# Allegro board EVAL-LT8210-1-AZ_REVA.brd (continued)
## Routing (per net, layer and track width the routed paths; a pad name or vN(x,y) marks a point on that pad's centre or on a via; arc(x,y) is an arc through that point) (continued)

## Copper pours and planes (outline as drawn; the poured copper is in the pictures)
GND_POWER on TOP: 66.04,222.88 176.35,222.88 176.35,149.35 138.23,149.35 137.97,149.61 137.97,164.59 137.59,164.97 103.48,164.97 102.03,163.52 102.03,149.02 59.39,149.02 59.39,162.81 32.51,162.81 32.51,218.19 54.86,218.19 55.17,218.49 55.17,220.85 66.04,220.85 ; 1 cut-out
GND_POWER on TOP: 190.2,160.45 190.2,156.79 195.63,156.79 195.63,160.45
GND_POWER on TOP: 66.04,133.1 176.35,133.1 176.35,62.23 138.18,62.23 137.92,62.48 137.92,77.34 137.41,77.85 103.48,77.85 102.03,76.4 102.03,61.72 59.39,61.72 59.39,75.56 32.51,75.56 32.51,128.4 54.86,128.4 55.17,128.7 55.17,131.19 66.04,131.19
GND_POWER on TOP: 66.04,312.67 176.35,312.67 176.35,239.4 138.21,239.4 137.96,239.65 137.96,254.5 137.58,254.88 103.48,254.88 101.98,253.38 101.98,239.45 60.01,239.45 60.01,252.73 32.51,252.73 32.51,307.97 54.86,307.97 55.17,308.28 55.17,310.77 66.04,310.77
GND_POWER on TOP: 12.06,160.45 12.06,156.79 17.5,156.79 17.5,160.45
GND_POWER on TOP: 66.32,45.85 176.35,45.85 176.35,2.54 32.51,2.54 32.51,41.15 54.86,41.15 55.17,41.45 55.17,43.57 66.32,43.57
GND_POWER on TOP: 32.65,356.62 32.65,342.54 59.87,342.54 59.87,328.6 101.98,328.6 101.98,343.19 103.48,344.69 137.58,344.69 137.96,344.31 137.96,329.18 138.21,328.93 176.35,328.93 176.35,356.62
GND_POWER on TOP, L5_VCC: 6.98,174.5 22.23,174.5
GND_POWER on TOP, L5_VCC: 185.29,196.72 200.53,196.72
GND_POWER on TOP, L5_VCC: 6.98,197.36 22.23,197.36
GND_POWER on TOP, L5_VCC: 185.29,173.86 200.53,173.86
GND_POWER on BOTTOM: 32.51,356.62 203.2,356.62 203.2,2.54 32.51,2.54 32.51,162.8 2.54,162.8 2.54,209.03 31.6,209.03 32.51,209.94
GND_POWER on L2_GND, L3_SIG, L4_GND, L5_VCC: 2.54,356.62 203.2,356.62 203.2,2.54 2.54,2.54
VDD on TOP: 51.86,22.99 51.86,21.86 51.55,21.86 51.41,21.72 51.41,20.45 50.62,20.45 50.62,22.22 46.76,22.22 46.69,22.3 46.69,22.91 46.76,22.99
VDD on TOP: 50.8,30.48 50.8,30.1 53.09,30.1 53.09,30.61 52.2,31.5 51.82,31.5
VIN on TOP: 72.39,171.96 72.39,167.89 73.28,167.01 92.58,167.01 94.61,169.04 94.61,173.36 93.09,173.36 93.09,170.43 91.06,168.4 75.56,168.4 74.29,169.67 74.29,171.96
VIN on TOP: 76.58,91.57 75.95,92.2 25.4,92.2 24,90.8 24,89.53 25.53,88.01 76.45,88.01 76.58,88.14
VIN on TOP: 32.02,356.62 32.02,2.54 2.67,2.54 2.67,356.62
VIN on TOP: 67.83,178.05 30.99,178.05 30.99,173.36 65.28,173.36 67.94,170.69 74.29,170.69 74.29,172.59 75.06,173.36 75.06,174.62 71.24,174.62
VIN on BOTTOM: 31.8,162.17 2.54,162.17 2.54,2.54 31.98,2.54 31.98,161.99
VIN on BOTTOM: 31.32,209.72 2.54,209.72 2.54,356.62 31.85,356.62 31.85,210.25
VIN on L2_GND, L3_SIG, L4_GND: 7.11,273.69 22.35,273.69
VIN on L2_GND, L3_SIG, L4_GND: 7.11,94.36 22.35,94.36
VIN on L5_VCC: 32.02,356.62 32.02,2.54 2.67,2.54 2.67,356.62
(no net) on TOP: 115.71,30.61 115.71,31.9 115.67,31.94 114.1,31.94 113.8,31.65 112.46,31.65 112.46,30.85 112.7,30.61
(no net) on TOP: 112.57,26.37 112.29,26.37 112.29,26.85 111.66,27.48 111.66,29.26 111.81,29.41 112.42,29.41 112.57,29.26
(no net) on L3_SIG: 91.95,63.37 94.74,60.58 94.74,40.87 106.38,29.24 111.79,29.24 111.94,29.39 112.32,29.39 112.5,29.21 112.5,28.14 105.97,28.14 93.73,40.39 93.73,60.07 91.31,62.48 69.71,62.48 69.58,62.6 69.58,63.75 69.71,63.88 70.87,63.88 70.99,63.75 70.99,63.5 71.12,63.37 82.7,63.37 82.7,63.75 82.83,63.88 83.57,63.88 83.69,63.75 83.69,63.5 83.82,63.37
EXTVCC_1 on TOP (solid shape): 115.71,31.9 115.71,30.61 112.7,30.61 112.46,30.85 112.46,31.65 113.8,31.65 114.1,31.94 115.67,31.94
EXTVCC_2 on TOP: 115.71,117.86 115.71,119.15 115.67,119.19 114.1,119.19 113.8,118.9 112.46,118.9 112.46,118.1 112.7,117.86
EXTVCC_3 on TOP: 115.71,207.64 115.71,208.94 115.67,208.98 114.1,208.98 113.8,208.69 112.46,208.69 112.46,207.89 112.7,207.64
EXTVCC_4 on TOP: 115.71,297.43 115.71,298.73 115.67,298.77 114.1,298.77 113.8,298.48 112.46,298.48 112.46,297.68 112.7,297.43
UNNAMED_2_ADLT82101_I27_SW1 on TOP: 95.78,73.23 95.78,62.57 95.99,62.37 101.68,62.37 102.02,62.71 102.02,73.2 101.82,73.41 95.96,73.41
UNNAMED_2_ADLT82101_I27_SW1 on TOP: 71.92,64.39 71.92,62.61 71.99,62.43 72.17,62.36 75.65,62.36 75.83,62.43 75.91,62.61 75.91,68.12 75.83,68.3 75.65,68.38 75.43,68.38 75.33,68.4 75.25,68.45 75.17,68.53 75.11,68.61 75.1,68.71 75.1,73.15 74.97,73.28 70.65,73.28 70.57,73.2 70.57,68.8 70.55,68.7 70.5,68.62 70.33,68.45 70.25,68.4 70.15,68.38 69.84,68.38 69.66,68.3 69.58,68.12 69.58,64.52 71.79,64.52
UNNAMED_2_ADLT82101_I27_SW1 on TOP: 88.91,62.65 88.84,62.47 88.66,62.4 85.12,62.4 84.94,62.47 84.86,62.65 84.86,66.04 84.73,66.17 82.7,66.17 82.7,68.12 82.78,68.3 82.96,68.38 83.16,68.38 83.25,68.4 83.34,68.45 83.47,68.58 83.52,68.66 83.54,68.76 83.54,73.15 83.67,73.28 87.99,73.28 88.01,73.25 88.01,68.79 88.03,68.69 88.09,68.61 88.23,68.46 88.31,68.41 88.41,68.39 88.66,68.39 88.84,68.32 88.91,68.14
UNNAMED_2_ADLT82101_I27_SW1 on BOTTOM: 69.82,73.41 69.57,73.15 69.57,62.73 70.07,62.23 76.43,62.23 76.56,62.36 76.56,63.88 76.68,64.01 84.81,64.01 84.94,63.88 84.94,62.36 85.19,62.1 89,62.1 89.26,62.36 89.26,63.88 89.38,64.01 95.58,64.01 95.58,62.36 101.35,62.36 101.35,73.41
UNNAMED_2_ADLT82101_I27_SW1 on L5_VCC: 69.82,73.41 69.57,73.15 69.57,62.36 101.35,62.36 101.35,73.41
UNNAMED_2_ADLT82101_I27_SW2 on TOP: 159.44,62.23 159.26,62.3 159.18,62.48 159.18,66.04 159.05,66.17 157.1,66.17 157.1,68.07 157.17,68.25 157.35,68.33 157.64,68.33 157.74,68.35 157.82,68.4 157.91,68.49 157.97,68.58 157.99,68.67 157.99,73.1 158.04,73.15 162.36,73.15 162.41,73.1 162.41,68.66 162.43,68.56 162.48,68.48 162.56,68.4 162.64,68.35 162.74,68.33 163.04,68.33 163.22,68.25 163.3,68.07 163.3,62.48 163.22,62.3 163.04,62.23
UNNAMED_2_ADLT82101_I27_SW2 on TOP: 122.94,77.22 122.68,76.96 122.68,46.74 122.94,46.48 137.05,46.48 137.3,46.74 137.3,76.96 137.05,77.22
UNNAMED_2_ADLT82101_I27_SW2 on TOP: 150.29,62.48 150.22,62.3 150.04,62.23 146.43,62.23 146.25,62.3 146.18,62.48 146.18,64.44 146.05,64.57 144.11,64.57 144.11,68.07 144.18,68.25 144.36,68.33 144.62,68.33 144.72,68.35 144.8,68.4 144.91,68.51 144.96,68.59 144.98,68.69 144.98,73.1 145.03,73.15 149.35,73.15 149.4,73.1 149.4,68.63 149.42,68.54 149.48,68.46 149.53,68.4 149.61,68.35 149.71,68.33 150.04,68.33 150.22,68.25 150.29,68.07
UNNAMED_2_ADLT82101_I27_SW2 on BOTTOM: 122.94,77.22 122.68,76.96 122.68,46.74 122.96,46.46 136.89,46.46 137.3,46.86 137.3,61.62 137.92,62.24 163,62.24 163.31,62.55 163.31,72.9 162.8,73.41 142.62,73.41 142.24,73.79 142.24,74.55 142.11,74.68 137.54,74.68 137.29,74.93 137.29,76.83 136.91,77.22
UNNAMED_2_ADLT82101_I27_SW2 on L5_VCC: 122.94,77.22 122.68,76.96 122.68,46.74 122.96,46.46 136.89,46.46 137.93,47.5 137.93,61.35 138.19,61.61 162.37,61.61 163.31,62.55 163.31,72.9 162.8,73.41 142.62,73.41 142.24,73.79 142.24,74.55 142.11,74.68 137.54,74.68 137.29,74.93 137.29,76.83 136.91,77.22
UNNAMED_2_ADLT82101_I27_TG1 on TOP (solid shape): 112.57,29.26 112.57,26.37 112.29,26.37 112.29,26.85 111.66,27.48 111.66,29.26 111.81,29.41 112.42,29.41
UNNAMED_2_ADLT82101_I27_TG1 on L3_SIG (solid shape): 70.99,63.75 70.99,63.5 71.12,63.37 82.7,63.37 82.7,63.75 82.83,63.88 83.57,63.88 83.69,63.75 83.69,63.5 83.82,63.37 91.95,63.37 94.74,60.58 94.74,40.87 106.38,29.24 111.79,29.24 111.94,29.39 112.32,29.39 112.5,29.21 112.5,28.14 105.97,28.14 93.73,40.39 93.73,60.07 91.31,62.48 69.71,62.48 69.58,62.6 69.58,63.75 69.71,63.88 70.87,63.88
UNNAMED_2_ADLT82101_I27_TG2 on L3_SIG: 141.66,63.8 157.75,63.8 157.75,62.41 141.78,62.41 127.63,48.26 127.63,30.28 121.77,24.41 118.85,24.41 118.77,24.49 118.77,25.76 118.87,25.86 121.28,25.86 126.62,31.19 126.62,48.77
UNNAMED_2_ADLT82101_I27_VIN on TOP: 111.33,23.88 111.33,23.57 109.85,23.57 109.47,23.19 107.75,23.19 107.54,22.99 105,22.99 105,26.72 106.98,26.72 109.83,23.88
UNNAMED_2_CAP_I39_N1 on TOP: 28.04,47.18 28.04,44.15 32,44.15 32,47.05 31.88,47.18
UNNAMED_2_CAP_I39_N1 on TOP: 30.09,59.57 30.09,58.35 30.21,58.22 31.86,58.22 31.99,58.35 31.99,59.57 31.88,59.68 30.2,59.68
UNNAMED_2_CAP_I39_N1 on L3_SIG: 30.23,59.82 30.23,45.85 30.48,45.59 31.75,45.59 32,45.85 32,59.82 31.88,59.94 30.35,59.94
UNNAMED_2_CAP_I149_N2 on TOP: 176.35,61.59 176.34,57.91 173.99,57.91 173.99,56.13 176.28,56.13 176.35,46.48 138.16,46.48 137.93,46.71 137.93,61.34 138.19,61.59
UNNAMED_2_CAP_I149_N2 on BOTTOM: 138.19,61.61 137.93,61.35 137.93,46.71 138.19,46.46 175.94,46.46 176.35,46.86 176.35,61.29 176.03,61.61
UNNAMED_2_CAP_I149_N2 on L5_VCC: 138.19,61.61 137.93,61.35 137.93,46.71 138.19,46.46 175.04,46.46 176.39,47.8 176.39,61.21 176,61.61
UNNAMED_2_CAPP_I42_N1 on TOP: 32.77,75.06 59.37,75.06 59.37,61.72 96.32,61.72 96.32,59.42 106.17,59.42 106.17,46.61 106.04,46.48 61.34,46.48 61.34,53.98 59.39,53.98 59.39,46.48 55.12,46.48 54.58,45.95 54.58,42.19 54.18,41.78 32.89,41.78 32.64,42.04 32.64,74.93
UNNAMED_2_CAPP_I42_N1 on BOTTOM: 32.88,75.06 59.39,75.06 59.39,61.72 96.33,61.72 96.33,59.31 106.17,59.31 106.17,46.61 106.04,46.48 55.12,46.48 54.58,45.95 54.58,42.19 54.18,41.78 33.01,41.78 32.63,42.16 32.63,74.8
UNNAMED_2_CAPP_I42_N1 on L5_VCC: 32.88,75.06 59.39,75.06 59.39,61.72 96.33,61.72 96.33,59.31 106.17,59.31 106.17,46.61 106.04,46.48 61.34,46.48 61.34,53.34 59.39,53.34 59.39,46.48 55.12,46.48 54.58,45.95 54.58,42.19 54.18,41.78 33.01,41.78 32.63,42.16 32.63,74.8
UNNAMED_2_IND_I187_N1 on TOP: 121.79,77.22 103.68,77.22 102.65,76.19 102.65,62.71 103.01,62.36 107.76,62.36 108.25,61.86 108.25,59.93 107.75,59.42 106.81,59.42 106.81,46.48 121.67,46.48 121.92,46.74 121.92,77.09
UNNAMED_2_IND_I187_N1 on BOTTOM, L5_VCC: 121.79,77.22 103.68,77.22 103.38,76.91 103.38,62.81 103.63,62.56 106.81,62.56 106.81,46.48 121.92,46.48 121.92,77.09
UNNAMED_2_NCTESTPAD_I95_N1 on TOP: 69.83,75.44 71.07,75.44 71.18,75.33 71.18,73.94 71.16,73.91 69.84,73.91 69.7,74.06 69.7,75.31
UNNAMED_2_NCTESTPAD_I95_N1 on TOP: 82.84,75.42 84.09,75.42 84.2,75.31 84.2,73.94 84.17,73.91 82.86,73.91 82.73,74.04 82.73,75.31
UNNAMED_2_NCTESTPAD_I95_N1 on L3_SIG: 70.74,75.44 70.87,75.31 70.87,74.93 70.99,74.8 78.61,74.8 78.74,74.93 78.74,75.18 78.87,75.31 80.01,75.31 80.14,75.18 80.14,74.93 80.26,74.8 82.4,74.8 82.52,74.93 82.52,75.31 82.65,75.44 83.44,75.44 83.57,75.31 83.57,74.93 83.67,74.83 108.05,74.83 110.49,72.39 110.49,43.93 119.72,34.7 119.72,33.52 118.47,33.52 118.47,34.48 109.6,43.35 109.6,72.01 107.57,74.04 69.63,74.04 69.51,74.17 69.51,75.31 69.63,75.44
UNNAMED_2_NCTESTPAD_I107_N1 on TOP: 158.67,75.31 158.67,73.91 158.55,73.79 157.21,73.79 157.1,73.9 157.1,75.31 157.23,75.44 158.55,75.44
UNNAMED_2_NCTESTPAD_I107_N1 on TOP: 144.24,75.44 145.54,75.44 145.67,75.31 145.67,73.91 145.54,73.79 144.22,73.79 144.09,73.91 144.09,75.29
UNNAMED_2_NCTESTPAD_I107_N1 on L3_SIG: 143.18,75.23 157.75,75.23 157.75,73.86 143.33,73.86 121.51,52.04 121.51,33.52 120.24,33.52 120.24,52.3
UNNAMED_3_ADLT82101_I10_SW1 on TOP: 95.78,250.15 95.78,239.66 95.99,239.46 101.69,239.46 101.98,239.75 101.98,250.11 101.77,250.33 95.96,250.33
UNNAMED_3_ADLT82101_I10_SW1 on TOP: 71.87,241.33 71.87,239.5 71.89,239.47 75.65,239.47 75.83,239.55 75.91,239.73 75.91,245.16 75.83,245.34 75.65,245.41 75.4,245.41 75.31,245.43 75.22,245.49 75.07,245.65 75.01,245.73 74.99,245.82 74.99,250.05 74.71,250.33 70.7,250.33 70.57,250.2 70.57,245.84 70.55,245.74 70.5,245.66 70.28,245.44 70.2,245.38 70.1,245.36 69.82,245.36 69.64,245.29 69.57,245.11 69.57,241.55 71.64,241.55
UNNAMED_3_ADLT82101_I10_SW1 on TOP: 88.89,239.71 88.81,239.53 88.63,239.46 85.09,239.46 84.91,239.53 84.84,239.71 84.84,242.82 84.45,243.21 82.72,243.21 82.72,245.16 82.79,245.34 82.97,245.41 83.17,245.41 83.27,245.43 83.35,245.49 83.52,245.66 83.57,245.74 83.59,245.84 83.59,250.11 83.79,250.32 87.63,250.32 88.01,249.94 88.01,245.82 88.03,245.73 88.09,245.65 88.24,245.49 88.32,245.43 88.42,245.41 88.63,245.41 88.81,245.34 88.89,245.16
UNNAMED_3_ADLT82101_I10_SW1 on BOTTOM: 69.82,250.44 69.57,250.19 69.57,239.45 76.56,239.45 76.56,240.92 76.68,241.05 84.81,241.05 84.94,240.92 84.94,239.45 89.26,239.45 89.26,240.92 89.38,241.05 95.58,241.05 95.58,239.45 101.35,239.45 101.35,250.44
UNNAMED_3_ADLT82101_I10_SW1 on L5_VCC: 69.82,250.33 69.57,250.08 69.57,239.45 101.35,239.45 101.35,250.33
UNNAMED_3_ADLT82101_I10_SW2 on TOP: 150.29,239.65 150.22,239.47 150.04,239.4 146.43,239.4 146.25,239.47 146.18,239.65 146.18,241.49 146.05,241.62 144.11,241.62 144.11,245.11 144.18,245.29 144.36,245.36 144.64,245.36 144.73,245.38 144.82,245.44 144.91,245.53 144.96,245.61 144.98,245.71 144.98,250.16 149.15,250.16 149.4,249.91 149.4,245.7 149.42,245.6 149.48,245.52 149.56,245.44 149.64,245.38 149.74,245.36 150.04,245.36 150.22,245.29 150.29,245.11
UNNAMED_3_ADLT82101_I10_SW2 on TOP: 159.51,239.34 159.33,239.42 159.26,239.6 159.26,242.82 158.88,243.21 157.11,243.21 157.11,245.11 157.19,245.29 157.37,245.36 157.64,245.36 157.74,245.38 157.82,245.44 157.91,245.53 157.97,245.61 157.99,245.71 157.99,250.09 162.15,250.09 162.39,249.85 162.39,245.71 162.41,245.61 162.47,245.53 162.56,245.44 162.64,245.38 162.74,245.36 163.03,245.36 163.21,245.29 163.28,245.11 163.28,239.6 163.21,239.42 163.03,239.34
UNNAMED_3_ADLT82101_I10_SW2 on TOP: 122.94,254.25 122.68,254 122.68,223.77 122.94,223.52 136.79,223.52 137.17,223.9 137.17,253.87 136.79,254.25
UNNAMED_3_ADLT82101_I10_SW2 on BOTTOM: 122.94,254.25 122.68,254 122.68,223.77 122.96,223.49 136.75,223.49 137.16,223.9 137.16,238.72 137.78,239.34 162.99,239.34 163.3,239.65 163.3,249.94 162.79,250.44 142.62,250.44 142.24,250.82 142.24,251.59 142.11,251.71 137.41,251.71 137.16,251.97 137.16,253.87 136.78,254.25
UNNAMED_3_ADLT82101_I10_SW2 on L5_VCC: 122.94,254.25 122.68,254 122.68,223.77 122.96,223.49 136.75,223.49 137.16,223.9 137.16,238.24 137.64,238.72 163,238.72 163.31,239.03 163.31,249.94 162.8,250.44 142.62,250.44 142.24,250.82 142.24,251.59 142.11,251.71 137.41,251.71 137.16,251.97 137.16,253.87 136.78,254.25
UNNAMED_3_ADLT82101_I10_TG1 on TOP: 112.57,203.4 112.29,203.4 112.29,203.89 111.66,204.52 111.66,206.3 111.81,206.45 112.42,206.45 112.57,206.3
UNNAMED_3_ADLT82101_I10_TG1 on L3_SIG: 91.69,240.41 94.74,237.36 94.74,217.91 106.37,206.27 111.81,206.27 111.96,206.43 112.34,206.43 112.5,206.27 112.5,205.18 105.97,205.18 93.73,217.42 93.73,236.86 91.06,239.52 69.71,239.52 69.58,239.64 69.58,240.79 69.71,240.92 70.87,240.92 70.99,240.79 70.99,240.54 71.12,240.41 82.7,240.41 82.7,240.79 82.83,240.92 83.57,240.92 83.69,240.79 83.69,240.54 83.82,240.41
UNNAMED_3_ADLT82101_I10_TG2 on TOP: 120.45,202.63 120.37,202.81 120.19,202.89 119.24,202.89 119.09,202.82 119.02,202.67 119.02,201.64 119.09,201.51 119.23,201.46 120.19,201.46 120.37,201.54 120.45,201.72
UNNAMED_3_ADLT82101_I10_TG2 on L3_SIG: 141.4,240.84 157.91,240.84 157.91,239.4 141.48,239.4 127.63,225.55 127.63,207.31 121.77,201.45 119.13,201.45 118.97,201.6 118.97,202.79 119.13,202.95 121.39,202.95 126.62,208.18 126.62,226.06
UNNAMED_3_ADLT82101_I10_VIN on TOP: 111.33,200.91 111.33,200.61 109.85,200.61 109.47,200.23 107.75,200.23 107.54,200.02 105,200.02 105,203.76 106.98,203.76 109.83,200.91
UNNAMED_3_CAP_I22_N1 on TOP: 28.02,224.21 28.02,221.21 32,221.21 32,224.21
UNNAMED_3_CAP_I22_N1 on TOP: 30.1,236.61 30.1,235.39 30.23,235.27 31.88,235.27 32,235.39 32,236.61 31.89,236.73 30.21,236.73
UNNAMED_3_CAP_I22_N1 on L3_SIG: 30.23,236.85 30.23,222.88 30.48,222.63 31.75,222.63 32,222.88 32,236.85 31.88,236.98 30.35,236.98
UNNAMED_3_CAP_I128_N2 on TOP: 176.35,238.71 176.35,234.7 174.12,234.7 174.12,232.92 176.35,232.92 176.35,223.52 138.05,223.52 137.79,223.77 137.79,238.51 138,238.71
UNNAMED_3_CAP_I128_N2 on BOTTOM: 138.05,238.71 137.79,238.46 137.79,223.75 138.05,223.49 176.04,223.49 176.36,223.81 176.36,238.34 175.99,238.71
UNNAMED_3_CAP_I128_N2 on L5_VCC: 138.05,238.71 137.79,238.46 137.79,223.75 138.05,223.49 174.83,223.49 176.39,225.06 176.39,238.34 176.02,238.71
UNNAMED_3_CAPP_I25_N1 on TOP: 32.64,251.97 32.64,219.1 32.89,218.85 54.11,218.85 54.52,219.25 54.52,222.99 55.05,223.52 59.39,223.52 59.39,231.01 61.34,231.01 61.34,223.52 105.92,223.52 106.04,223.65 106.04,236.47 96.32,236.47 96.32,238.82 59.39,238.82 59.39,252.09 32.77,252.09
UNNAMED_3_CAPP_I25_N1 on BOTTOM: 32.77,252.09 59.39,252.09 59.39,238.76 96.32,238.76 96.32,236.47 106.04,236.47 106.04,223.65 105.92,223.52 55.12,223.52 54.58,222.99 54.58,219.1 54.18,218.69 32.89,218.69 32.51,219.07 32.51,251.84
UNNAMED_3_CAPP_I25_N1 on L5_VCC: 32.89,252.09 59.39,252.09 59.39,238.76 96.32,238.76 96.32,236.47 106.17,236.47 106.17,223.65 106.04,223.52 61.34,223.52 61.34,230.38 59.39,230.38 59.39,223.52 55.12,223.52 54.58,222.99 54.58,219.1 54.18,218.69 33.02,218.69 32.64,219.07 32.64,251.84
UNNAMED_3_IND_I87_N1 on TOP: 121.79,254.25 103.68,254.25 102.62,253.19 102.62,239.76 102.95,239.43 107.76,239.43 108.25,238.94 108.25,237.02 107.71,236.47 106.68,236.47 106.68,223.52 121.67,223.52 121.92,223.77 121.92,254.13
UNNAMED_3_IND_I87_N1 on BOTTOM, L5_VCC: 121.79,254.25 103.68,254.25 103.38,253.95 103.38,239.85 103.63,239.6 106.68,239.6 106.68,223.52 121.92,223.52 121.92,254.13
UNNAMED_3_NCTESTPAD_I76_N1 on TOP: 69.84,252.48 71.06,252.48 71.18,252.35 71.18,251.09 71.06,250.96 69.85,250.96 69.72,251.1 69.72,252.35
UNNAMED_3_NCTESTPAD_I76_N1 on TOP: 82.84,252.49 84.06,252.49 84.2,252.35 84.2,251.09 84.07,250.96 82.92,250.96 82.73,251.16 82.73,252.37
UNNAMED_3_NCTESTPAD_I76_N1 on L3_SIG: 70.74,252.48 70.87,252.35 70.87,251.97 70.99,251.84 78.61,251.84 78.74,251.97 78.74,252.22 78.87,252.35 80.01,252.35 80.14,252.22 80.14,251.97 80.26,251.84 82.4,251.84 82.52,251.97 82.52,252.35 82.65,252.48 83.44,252.48 83.57,252.35 83.57,251.97 83.67,251.87 108.05,251.87 110.49,249.43 110.49,220.97 119.72,211.73 119.72,210.55 118.47,210.55 118.47,211.52 109.6,220.38 109.6,249.05 107.57,251.08 69.63,251.08 69.51,251.21 69.51,252.35 69.63,252.48
UNNAMED_3_NCTESTPAD_I88_N1 on TOP: 158.67,252.4 158.67,251.08 158.53,250.93 157.24,250.93 157.11,251.07 157.11,252.38 157.25,252.53 158.55,252.53
UNNAMED_3_NCTESTPAD_I88_N1 on TOP: 145.67,252.22 145.67,250.97 145.56,250.86 144.4,250.86 144.27,250.99 144.27,252.21 144.37,252.31 145.58,252.31
UNNAMED_3_NCTESTPAD_I88_N1 on L3_SIG: 143.18,252.27 157.75,252.27 157.75,250.9 143.33,250.9 121.51,229.08 121.51,210.55 120.24,210.55 120.24,229.34
UNNAMED_4_ADLT82101_I10_SW1 on TOP: 88.91,329.49 88.84,329.31 88.66,329.24 85.12,329.24 84.94,329.31 84.86,329.49 84.86,332.61 84.48,332.99 82.74,332.99 82.74,334.94 82.81,335.12 82.99,335.2 83.19,335.2 83.29,335.22 83.37,335.27 83.54,335.44 83.6,335.52 83.62,335.62 83.62,339.9 83.82,340.1 87.66,340.1 88.04,339.72 88.04,335.61 88.06,335.51 88.11,335.43 88.27,335.27 88.35,335.22 88.45,335.2 88.66,335.2 88.84,335.12 88.91,334.94
UNNAMED_4_ADLT82101_I10_SW1 on TOP: 71.88,331.1 71.88,329.5 71.96,329.32 72.14,329.25 75.63,329.25 75.81,329.32 75.88,329.5 75.88,334.95 75.81,335.13 75.63,335.2 75.4,335.2 75.31,335.22 75.22,335.28 75.07,335.43 75.01,335.52 74.99,335.61 74.99,339.83 74.71,340.11 70.7,340.11 70.57,339.98 70.57,335.61 70.55,335.52 70.5,335.43 70.34,335.28 70.26,335.22 70.16,335.2 69.82,335.2 69.64,335.13 69.57,334.95 69.57,331.34 71.64,331.34
UNNAMED_4_ADLT82101_I10_SW1 on TOP: 95.78,339.94 95.78,329.45 95.99,329.25 101.71,329.25 101.98,329.51 101.98,339.93 101.79,340.12 95.96,340.12
UNNAMED_4_ADLT82101_I10_SW1 on BOTTOM: 69.81,340.12 69.56,339.86 69.56,329.25 76.56,329.25 76.56,330.71 76.68,330.83 84.81,330.83 84.94,330.71 84.94,329.25 89.26,329.25 89.26,330.71 89.38,330.83 95.58,330.83 95.58,329.25 101.35,329.25 101.35,340.12
UNNAMED_4_ADLT82101_I10_SW1 on L5_VCC: 69.81,340.12 69.56,339.86 69.56,329.25 101.35,329.25 101.35,340.12
UNNAMED_4_ADLT82101_I10_SW2 on TOP: 150.25,329.18 150.18,329 150,328.93 146.43,328.93 146.25,329 146.18,329.18 146.18,330.81 146,330.99 144.2,330.99 144.09,331.09 144.09,334.9 144.17,335.08 144.35,335.15 144.64,335.15 144.73,335.17 144.82,335.23 144.91,335.32 144.96,335.4 144.98,335.5 144.98,339.93 149.11,339.93 149.4,339.64 149.4,335.49 149.42,335.39 149.48,335.31 149.56,335.23 149.64,335.17 149.74,335.15 150,335.15 150.18,335.08 150.25,334.9
UNNAMED_4_ADLT82101_I10_SW2 on TOP: 159.23,329.06 159.23,332.63 158.85,333.01 157.07,333.01 157.07,334.9 157.15,335.08 157.33,335.15 157.63,335.15 157.72,335.17 157.81,335.23 157.89,335.31 157.94,335.39 157.96,335.49 157.96,339.88 162.13,339.88 162.38,339.62 162.38,335.49 162.4,335.39 162.46,335.31 162.54,335.23 162.62,335.17 162.72,335.15 163.03,335.15 163.21,335.08 163.28,334.9 163.28,329.18 163.21,329 163.03,328.93 159.36,328.93
UNNAMED_4_ADLT82101_I10_SW2 on TOP: 122.94,344.04 122.68,343.79 122.68,313.56 122.94,313.31 136.93,313.31 137.31,313.69 137.31,343.66 136.93,344.04
UNNAMED_4_ADLT82101_I10_SW2 on BOTTOM: 122.94,344.04 122.68,343.79 122.68,313.56 122.96,313.28 137.01,313.28 137.41,313.69 137.41,328.45 137.9,328.93 162.99,328.93 163.3,329.23 163.3,339.72 162.79,340.23 142.62,340.23 142.24,340.61 142.24,341.38 142.11,341.5 137.67,341.5 137.41,341.76 137.41,343.66 137.03,344.04
UNNAMED_4_ADLT82101_I10_SW2 on L5_VCC: 122.94,344.04 122.68,343.79 122.68,313.56 122.96,313.28 136.91,313.28 137.31,313.69 137.31,328.45 137.79,328.93 162.99,328.93 163.3,329.23 163.3,339.72 162.79,340.23 142.62,340.23 142.24,340.61 142.24,341.38 142.11,341.5 137.67,341.5 137.41,341.76 137.41,343.66 137.03,344.04
UNNAMED_4_ADLT82101_I10_TG1 on TOP: 112.57,293.19 112.29,293.19 112.29,293.67 111.66,294.31 111.66,296.09 111.81,296.24 112.42,296.24 112.57,296.09
UNNAMED_4_ADLT82101_I10_TG1 on L3_SIG: 91.57,330.2 94.74,327.03 94.74,307.7 106.37,296.06 111.76,296.06 111.91,296.21 112.42,296.21 112.57,296.06 112.57,294.94 105.99,294.94 93.73,307.21 93.73,326.52 90.93,329.31 69.71,329.31 69.58,329.43 69.58,330.58 69.71,330.71 70.87,330.71 70.99,330.58 70.99,330.33 71.12,330.2 82.7,330.2 82.7,330.58 82.83,330.71 83.57,330.71 83.69,330.58 83.69,330.33 83.82,330.2
UNNAMED_4_ADLT82101_I10_TG2 on TOP: 120.45,292.42 120.37,292.6 120.19,292.68 119.28,292.68 119.08,292.57 119,292.35 119,291.47 119.07,291.31 119.22,291.25 120.19,291.25 120.37,291.33 120.45,291.51
UNNAMED_4_ADLT82101_I10_TG2 on L3_SIG: 140.74,330.35 157.82,330.35 157.82,329.01 140.92,329.01 127.63,315.72 127.63,297.05 121.82,291.24 119.18,291.24 119,291.41 119,292.53 119.18,292.71 121.39,292.71 126.62,297.94 126.62,316.23
UNNAMED_4_ADLT82101_I10_VIN on TOP: 111.33,290.7 111.33,290.4 109.85,290.4 109.47,290.02 107.75,290.02 107.54,289.81 105,289.81 105,293.55 106.98,293.55 109.83,290.7
UNNAMED_4_CAP_I22_N1 on TOP: 30.1,327 30.1,325.82 30.23,325.69 31.88,325.69 32,325.82 32,327.14 30.24,327.14
UNNAMED_4_CAP_I22_N1 on TOP: 28.04,313.99 28.04,311 32,311 32,313.99
UNNAMED_4_CAP_I22_N1 on L3_SIG: 30.23,326.64 30.23,312.67 30.48,312.42 31.75,312.42 32,312.67 32,326.64 31.88,326.77 30.35,326.77
UNNAMED_4_CAP_I128_N2 on TOP: 176.35,328.27 176.35,324.61 174.12,324.61 174.12,322.83 176.35,322.83 176.35,313.28 138.2,313.28 137.95,313.54 137.95,328.27
UNNAMED_4_CAP_I128_N2 on BOTTOM: 138.05,328.27 137.79,328.02 137.79,313.54 138.05,313.28 176.04,313.28 176.35,313.59 176.35,328.03 176.11,328.27
UNNAMED_4_CAP_I128_N2 on L5_VCC: 138.2,328.27 137.95,328.02 137.95,313.54 138.2,313.28 174.87,313.28 176.39,314.81 176.39,327.84 175.96,328.27
UNNAMED_4_CAPP_I25_N1 on TOP: 32.64,341.76 32.64,308.95 32.89,308.7 54.18,308.7 54.58,309.11 54.58,312.78 55.12,313.31 59.39,313.31 59.39,320.8 61.34,320.8 61.34,313.31 106.04,313.31 106.17,313.44 106.17,326.26 96.32,326.26 96.32,328.6 59.23,328.6 59.23,341.88 32.77,341.88
UNNAMED_4_CAPP_I25_N1 on BOTTOM: 32.77,341.88 59.25,341.88 59.25,328.55 96.32,328.55 96.32,326.26 106.17,326.26 106.17,313.37 106.04,313.25 55.12,313.25 54.58,312.71 54.58,308.89 54.18,308.48 32.89,308.48 32.51,308.86 32.51,341.63
UNNAMED_4_CAPP_I25_N1 on L5_VCC: 32.77,341.88 59.23,341.88 59.23,328.56 96.32,328.56 96.32,326.26 106.17,326.26 106.17,313.37 106.04,313.25 61.34,313.25 61.34,320.17 59.39,320.17 59.39,313.25 55.12,313.25 54.58,312.71 54.58,309.11 54.18,308.7 32.89,308.7 32.51,309.08 32.51,341.63
UNNAMED_4_IND_I87_N1 on TOP: 121.79,344.04 103.68,344.04 102.62,342.98 102.62,329.51 102.88,329.25 107.98,329.25 108.25,328.97 108.25,326.87 107.65,326.26 106.78,326.26 106.78,313.31 121.67,313.31 121.92,313.56 121.92,343.92
UNNAMED_4_IND_I87_N1 on BOTTOM, L5_VCC: 121.79,344.04 103.68,344.04 103.38,343.74 103.38,329.5 103.63,329.25 106.81,329.25 106.81,313.25 121.92,313.25 121.92,343.92
UNNAMED_4_NCTESTPAD_I76_N1 on TOP: 69.84,342.26 71.07,342.26 71.18,342.15 71.18,340.85 71.07,340.74 69.82,340.74 69.71,340.86 69.71,342.13
UNNAMED_4_NCTESTPAD_I76_N1 on TOP: 82.86,342.26 84.09,342.26 84.2,342.16 84.2,340.85 84.09,340.74 82.87,340.74 82.74,340.87 82.74,342.15
UNNAMED_4_NCTESTPAD_I76_N1 on L3_SIG: 70.74,342.26 70.87,342.14 70.87,341.76 70.99,341.63 78.61,341.63 78.74,341.76 78.74,342.01 78.87,342.14 80.01,342.14 80.14,342.01 80.14,341.76 80.26,341.63 82.4,341.63 82.52,341.76 82.52,342.14 82.65,342.26 83.44,342.26 83.57,342.14 83.57,341.76 83.67,341.66 108.05,341.66 110.49,339.22 110.49,310.76 119.56,301.69 119.56,300.34 118.47,300.34 118.47,301.31 109.6,310.17 109.6,338.84 107.57,340.87 69.63,340.87 69.51,340.99 69.51,342.14 69.63,342.26
UNNAMED_4_NCTESTPAD_I88_N1 on TOP: 158.65,342.19 158.65,340.87 158.52,340.74 157.27,340.74 157.14,340.87 157.14,342.15 157.3,342.32 158.52,342.32
UNNAMED_4_NCTESTPAD_I88_N1 on TOP: 145.67,342.06 145.67,340.85 145.51,340.69 144.36,340.69 144.22,340.83 144.22,342.05 144.37,342.19 145.54,342.19
UNNAMED_4_NCTESTPAD_I88_N1 on L3_SIG: 143.05,342.06 157.75,342.06 157.75,340.69 143.2,340.69 121.51,319 121.51,300.36 120.22,300.36 120.22,319.23
UNNAMED_5_ADLT8631_I47_IND on TOP: 84.71,99.57 84.71,102.23 83.82,103.12 83.82,107.7 84.84,108.71 86.87,108.71 87.5,108.08 87.5,102.11 84.96,99.57
UNNAMED_5_ADLT8631_I47_SW on TOP: 75.82,110.49 75.82,107.19 79.5,103.5 79.5,100.46 79.63,100.33 80.77,100.33 81.03,100.58 81.03,103.38 81.91,104.27 81.91,110.36 81.66,110.62 75.95,110.62
UNNAMED_5_ADLT8631_I47_VIN on TOP: 71.75,101.22 71.75,96.27 72.52,95.5 73.53,95.5 77.34,91.69 77.34,88.14 77.47,88.01 78.99,88.01 79.25,88.27 79.25,89.79 79.88,90.42 81.15,90.42 81.15,93.6 79.5,95.25 77.09,95.25 76.33,96.01 76.33,101.09 76.07,101.35 71.88,101.35
UNNAMED_5_ADLT8631_I98_IND on TOP: 78.55,178.94 78.55,181.1 79.25,181.8 79.25,184.4 77.66,185.99 77.66,190.12 77.91,190.37 80.58,190.37 80.84,190.12 80.84,181.61 79.06,179.83 79.06,178.94
UNNAMED_5_ADLT8631_I98_SW on TOP: 75.18,178.82 75.18,190.12 74.8,190.5 71.37,190.5 70.48,189.61 70.48,181.23 70.87,180.85 73.79,180.85 74.04,180.59 74.04,178.94 74.17,178.82
UNNAMED_7_ADLT82101_I136_SW1 on TOP: 88.89,149.88 88.82,149.7 88.64,149.62 85.1,149.62 84.92,149.7 84.84,149.88 84.84,153.27 84.71,153.4 82.68,153.4 82.68,155.35 82.76,155.53 82.94,155.61 83.14,155.61 83.23,155.62 83.32,155.68 83.45,155.81 83.5,155.89 83.52,155.99 83.52,160.38 83.65,160.51 87.97,160.51 87.99,160.48 87.99,156.02 88.01,155.92 88.07,155.84 88.21,155.69 88.29,155.64 88.39,155.62 88.64,155.62 88.82,155.54 88.89,155.36
UNNAMED_7_ADLT82101_I136_SW1 on TOP: 71.88,151.64 71.88,149.86 71.96,149.68 72.14,149.61 75.68,149.61 75.86,149.68 75.93,149.86 75.93,155.37 75.86,155.55 75.68,155.63 75.4,155.63 75.31,155.65 75.22,155.7 75.07,155.86 75.13,155.86 75.08,155.94 75.06,156.04 75.06,160.31 74.82,160.55 70.57,160.55 70.57,156.05 70.55,155.95 70.5,155.87 70.33,155.7 70.25,155.65 70.15,155.63 69.82,155.63 69.64,155.55 69.57,155.37 69.57,151.76 71.75,151.76
UNNAMED_7_ADLT82101_I136_SW1 on TOP: 95.78,160.48 95.78,149.86 95.99,149.66 101.56,149.66 102.03,150.13 102.03,160.44 101.82,160.65 95.96,160.65
UNNAMED_7_ADLT82101_I136_SW1 on BOTTOM: 69.82,160.65 69.57,160.4 69.57,149.66 76.43,149.66 76.56,149.78 76.56,151.13 76.68,151.26 84.81,151.26 84.94,151.13 84.94,149.66 89.26,149.66 89.26,151.13 89.38,151.26 95.58,151.26 95.58,149.66 101.35,149.66 101.35,160.65
UNNAMED_7_ADLT82101_I136_SW1 on L5_VCC: 69.82,160.65 69.57,160.4 69.57,149.66 101.35,149.66 101.35,160.65
UNNAMED_7_ADLT82101_I136_SW2 on TOP: 159.5,149.35 159.32,149.43 159.25,149.61 159.25,153.04 158.86,153.42 157.11,153.42 157.11,155.32 157.19,155.5 157.37,155.57 157.64,155.57 157.74,155.59 157.82,155.65 157.91,155.74 157.97,155.82 157.99,155.92 157.99,160.3 162.15,160.3 162.41,160.05 162.41,155.91 162.43,155.81 162.48,155.73 162.56,155.65 162.64,155.59 162.74,155.57 163.04,155.57 163.22,155.5 163.3,155.32 163.3,149.61 163.22,149.43 163.04,149.35
UNNAMED_7_ADLT82101_I136_SW2 on TOP: 150.28,149.61 150.2,149.43 150.03,149.35 146.43,149.35 146.25,149.43 146.18,149.61 146.18,151.3 146.1,151.47 145.92,151.55 144.11,151.55 144.11,155.32 144.18,155.5 144.36,155.57 144.64,155.57 144.73,155.59 144.82,155.65 144.91,155.74 144.96,155.82 144.98,155.92 144.98,160.25 149.15,160.25 149.4,159.99 149.4,155.91 149.42,155.81 149.48,155.73 149.56,155.65 149.64,155.59 149.74,155.57 150.03,155.57 150.2,155.5 150.28,155.32
UNNAMED_7_ADLT82101_I136_SW2 on TOP: 122.94,164.29 122.68,164.03 122.68,133.98 122.94,133.73 136.96,133.73 137.34,134.11 137.34,163.91 136.96,164.29
UNNAMED_7_ADLT82101_I136_SW2 on BOTTOM: 122.94,164.29 122.68,164.03 122.68,133.98 122.96,133.71 136.93,133.71 137.34,134.11 137.34,148.87 137.82,149.35 163,149.35 163.31,149.66 163.31,160.15 162.8,160.65 142.62,160.65 142.24,161.04 142.24,161.8 142.11,161.92 137.67,161.92 137.41,162.18 137.41,163.91 137.03,164.29
UNNAMED_7_ADLT82101_I136_SW2 on L5_VCC: 122.94,164.29 122.68,164.03 122.68,133.98 122.96,133.71 136.93,133.71 137.34,134.11 137.34,148.87 137.82,149.35 163,149.35 163.31,149.66 163.31,160.15 162.8,160.65 142.62,160.65 142.24,161.04 142.24,161.8 142.11,161.92 137.59,161.92 137.34,162.18 137.34,163.91 136.96,164.29
UNNAMED_7_ADLT82101_I136_TG1 on TOP: 112.57,113.61 112.29,113.61 112.29,114.1 111.66,114.73 111.66,116.51 111.81,116.66 112.42,116.66 112.57,116.51
UNNAMED_7_ADLT82101_I136_TG1 on L3_SIG: 91.82,150.62 94.74,147.7 94.74,128.12 106.38,116.48 111.79,116.48 111.94,116.64 112.34,116.64 112.52,116.46 112.52,115.39 105.97,115.39 93.73,127.64 93.73,147.19 91.19,149.73 69.71,149.73 69.58,149.85 69.58,151 69.71,151.13 70.87,151.13 70.99,151 70.99,150.75 71.12,150.62 82.7,150.62 82.7,151 82.83,151.13 83.57,151.13 83.69,151 83.69,150.75 83.82,150.62
UNNAMED_7_ADLT82101_I136_TG2 on TOP: 119.2,113.13 119.06,113.06 119,112.9 119,111.84 119.06,111.69 119.2,111.63 120.24,111.63 120.41,111.72 120.47,111.89 120.47,112.95 120.4,113.08 120.27,113.13
UNNAMED_7_ADLT82101_I136_TG2 on L3_SIG: 140.89,150.93 157.87,150.93 157.87,149.56 141.05,149.56 127.64,136.14 127.64,117.45 121.84,111.66 119.1,111.66 119.02,111.73 119.02,113.03 119.1,113.11 121.31,113.11 126.62,118.42 126.62,136.65
UNNAMED_7_ADLT82101_I136_VIN on TOP: 111.33,111.12 111.33,110.82 109.86,110.82 109.47,110.44 107.75,110.44 107.54,110.24 105,110.24 105,113.97 106.99,113.97 109.83,111.12
UNNAMED_7_CAP_I21_N1 on TOP: 30.1,146.82 30.1,145.6 30.23,145.47 31.88,145.47 32,145.6 32,146.82 31.89,146.93 30.21,146.93
UNNAMED_7_CAP_I21_N1 on TOP: 28.16,134.39 28.16,131.33 32,131.33 32,134.39
UNNAMED_7_CAP_I21_N1 on L3_SIG: 30.23,147.07 30.23,133.1 30.48,132.84 31.75,132.84 32,133.1 32,147.07 31.88,147.19 30.35,147.19
UNNAMED_7_CAP_I127_N2 on TOP: 176.35,148.72 176.35,145.16 174.12,145.16 174.12,143.38 176.35,143.38 176.35,133.71 138.21,133.71 137.96,133.96 137.96,148.46 138.21,148.72
UNNAMED_7_CAP_I127_N2 on BOTTOM: 138.21,148.72 137.96,148.46 137.96,133.96 138.21,133.71 176.02,133.71 176.39,134.08 176.39,148.33 176,148.72
UNNAMED_7_CAP_I127_N2 on L5_VCC: 138.21,148.72 137.96,148.46 137.96,133.96 138.21,133.71 175.11,133.71 176.39,134.99 176.39,148.35 176.02,148.72
UNNAMED_7_CAPP_I24_N1 on TOP: 32.64,162.18 32.64,129.16 32.89,128.9 54.18,128.9 54.58,129.31 54.58,133.2 55.12,133.73 59.39,133.73 59.39,141.22 61.34,141.22 61.34,133.73 106.05,133.73 106.17,133.86 106.17,146.68 96.32,146.68 96.32,148.97 59.39,148.97 59.39,162.31 32.77,162.31
UNNAMED_7_CAPP_I24_N1 on BOTTOM: 32.77,162.31 59.39,162.31 59.39,148.97 96.32,148.97 96.32,146.68 106.17,146.68 106.17,133.86 106.05,133.73 55.12,133.73 54.58,133.2 54.58,129.31 54.18,128.9 32.89,128.9 32.51,129.29 32.51,162.05
UNNAMED_7_CAPP_I24_N1 on L5_VCC: 32.89,162.31 59.39,162.31 59.39,148.97 96.32,148.97 96.32,146.68 106.17,146.68 106.17,133.86 106.05,133.73 61.34,133.73 61.34,140.59 59.39,140.59 59.39,133.73 55.12,133.73 54.58,133.2 54.58,129.31 54.18,128.9 33.02,128.9 32.64,129.29 32.64,162.05
UNNAMED_7_IND_I86_N1 on TOP: 121.79,164.29 103.68,164.29 102.67,163.27 102.67,150.11 103.12,149.66 107.73,149.66 108.23,149.16 108.23,147.21 107.71,146.68 106.82,146.68 106.82,133.73 121.67,133.73 121.92,133.98 121.92,164.16
UNNAMED_7_IND_I86_N1 on BOTTOM: 121.79,164.29 103.68,164.29 103.38,163.98 103.38,150.06 103.63,149.81 106.82,149.81 106.82,133.73 121.92,133.73 121.92,164.16
UNNAMED_7_IND_I86_N1 on L5_VCC: 121.79,164.29 103.68,164.29 103.38,163.98 103.38,150.06 103.63,149.81 106.82,149.81 106.82,133.73 121.92,133.73 121.92,164.16
UNNAMED_7_NCTESTPAD_I75_N1 on TOP: 82.87,162.7 84.07,162.7 84.19,162.58 84.19,161.22 84.14,161.17 82.85,161.17 82.74,161.29 82.74,162.57
UNNAMED_7_NCTESTPAD_I75_N1 on TOP: 69.84,162.69 71.07,162.69 71.18,162.58 71.18,161.2 71.14,161.17 69.86,161.17 69.71,161.32 69.71,162.55
UNNAMED_7_NCTESTPAD_I75_N1 on L3_SIG: 70.74,162.69 70.87,162.56 70.87,162.18 70.99,162.05 78.61,162.05 78.74,162.18 78.74,162.43 78.87,162.56 80.01,162.56 80.14,162.43 80.14,162.18 80.26,162.05 82.4,162.05 82.52,162.18 82.52,162.56 82.65,162.69 83.44,162.69 83.57,162.56 83.57,162.18 83.67,162.08 108.05,162.08 110.49,159.64 110.49,131.18 119.72,121.95 119.72,120.76 118.47,120.76 118.47,121.73 109.6,130.59 109.6,159.26 107.57,161.29 69.63,161.29 69.51,161.42 69.51,162.56 69.63,162.69
UNNAMED_7_NCTESTPAD_I87_N1 on TOP: 145.67,162.39 145.67,161.12 145.54,161 144.37,161 144.27,161.09 144.27,162.43 144.37,162.52 145.54,162.52
UNNAMED_7_NCTESTPAD_I87_N1 on TOP: 158.67,162.56 158.67,161.29 158.55,161.16 157.4,161.16 157.26,161.3 157.26,162.57 157.38,162.69 158.55,162.69
UNNAMED_7_NCTESTPAD_I87_N1 on L3_SIG: 143.31,162.48 157.75,162.48 157.75,161.11 143.46,161.11 121.51,139.17 121.51,120.76 120.24,120.76 120.24,139.42
VOUT on TOP: 177.03,356.62 203.07,356.62 203.07,2.54 177.03,2.54 177.1,56.13 179.32,56.13 179.32,57.91 177.04,57.91 177.03,143.38 179.2,143.38 179.2,145.16 177.03,145.16 177.03,232.92 179.2,232.92 179.2,234.7 177.03,234.7 177.03,322.83 179.2,322.83 179.2,324.61 177.03,324.61
VOUT on BOTTOM: 192.82,161.12 203.2,161.12 203.2,2.54 177.03,2.54 177.03,156.75
VOUT on BOTTOM: 192.82,209.54 203.2,209.54 203.2,356.62 177.02,356.62 177.02,213.92
VOUT on L2_GND, L3_SIG, L4_GND: 185.29,273.69 200.53,273.69
VOUT on L2_GND, L3_SIG, L4_GND: 185.29,94.36 200.53,94.36
VOUT on L5_VCC: 177.03,356.62 203.2,356.62 203.2,2.54 177.03,2.54

Small or netless copper shapes (teardrops, artwork), in the pictures only: 36 on TOP

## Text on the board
BOTTOM: 08-080303 REV A
User.Comments: + | A | C | 3 | 4 | 2 | SEE NOTE#6 | SEE NOTE#5 | 6 PLACES | 8 PLACES | MFG_PN: 4705 | 5.    SEE DETAIL A TO INSTALL  KFH-032-10ET. | 6.    INSTALL THE FOLLOWING: | 7.    INSTALL THE FOLLOWING: SHUNT (MFG_PN: 2SN-BK-G) | STAND-OFF (MFG_PN:  1902C) AT SECONDARY SIDE | SCREW (MFG_PN: NY PMS 440 0025 PH) AT PRIMARY SIDE AND | JP1: PIN3 & PIN4 | JP2: PIN3 & PIN4 | NOT TO SCALE | DETAIL A | MFG_PN: KFH-032-10ET | WASHER, LOCK STEEL 3/64 | MFG_PN: 1477 | MFG_PN: 4703
Ref Des/Silkscreen Top: C | A | + | *XVCC4 | *XVCC3 | *XVCC2 | *XVCC1 | GND | VIN | MODE 2 | MODE 1 | VDD | CCM | DCM | NOT ALLOWED | PASS-THROUGH | SWITCHING MODE | VOUT | 08-080303 REV A | CONTROLLER WITH PASS-THROUGH | 100V FOUR PHASE BUCK-BOOST | 26V TO 80V | 48V, 20A MAX | EVAL-LT8210-1-AZ
PAGE_OUTLINE: FAB NOTES REVISION: 2ND NOVEMBER 2022 | J Wu | C Richlie | 03Sep24 | 8.   IMPEDANCE REQUIREMENTS: IF NO STACKUP IS DEFINED, THE VENDOR IS ALLOWED TO ADJUST THE DIELECTRIC | 13.  PLATING SPECIFICATION: | 9.   FILLET OPTIONS TO ENHANCE RELIABILITY AT PAD JUNCTIONS WHERE SPACING PERMITS. | 10.  THIEVING: | 11.  LAYER TO LAYER REGISTRATION SHALL BE WITHIN 0.003 INCHES. | 12.  DRILL SIZES ARE FINISHED HOLE SIZES. ALL HOLES SHALL BE LOCATED WITHIN 0.005 INCHES DTP,UNLESS SPECIFIED. | 14.  SURFACE FINISH: | 15.  SOLDERMASK: | 1.   DIMENSIONS ARE IN INCHES (EXCEPT WHERE NOTED). | ALL DOCUMENTS & SPECIFICATIONS REFERRED TO BELOW SHOULD BE THE LATEST REVISIONS. | 2.  BOARD MATERIAL:(USE CHECKED ITEMS) | 3.   ALL LAMINATES & BONDING MATERIALS SHOULD BE SELECTED FROM IPC-4101 OR IPC-4103,(TG>170 DEGC TD>300 DEGC) | 4.   REFER TO IPC-6010 SERIES, CLASS 2 FOR FABRICATION. | 5.   REFER TO LAMINATION DIAGRAM FOR OVERALL BOARD THICKNESS, TOLERANCE APPLIES AFTER ALL LAMINATION AND PLATING | 6.   BOW & TWIST NOT TO EXCEED 0.0075 INCHES (0.75%) PER LINEAR INCH AND SHOULD BE MEASURED PER IPC-TM-650, METHOD 2.4.22. | 7.   ACCEPTABILITY PER ADI SPECIFICATION TST00115. | 16.  APPLY SILKSCREEN TO BOTH SIDES USING A NON-CONDUCTIVE, EPOXY BASED INK PER ARTWORK. | RoHS COMPLIANCE NOTE: HOMOGENOUS MATERIALS IN THIS BOARD SHALL BE COMPLAINT WITH THE EU DIRECTIVE 2002/95/EC | ( ) FILLETS ALLOWED | (X) FILLETS NOT ALLOWED | ( ) VENDOR MAY ADD THIEVING TO COMPENSATE FOR LOW COPPER DENSITY AREAS MAINTAINING A MINIMUM | (X) VENDOR MAY NOT ADD THIEVING TO COMPENSATE FOR LOW COPPER DENSITY AREAS. | (X) LPI | ( ) OTHER_________ | COLOR | ( ) GREEN | (X) WHITE | ( ) OTHER | HINDER PROPER SOLDER WICKING. BARREL RELIEF ON SOLDERMASK ALLOWED IN UNFILLED VIA IN PAD HOLES. | (X) REFER TO LAMINATION DIAGRAM FOR FINISHED COPPER WEIGHT/THICKNESS REQUIRMENTS | (X) IMMERSION GOLD (ENIG) 1.58-3.94 MICRO INCHES OVER 118-236 MICRO INCHES MIN. OF ELECTROLESS NICKEL PER IPC-4552 | ( ) OSP (ORGANIC SOLDERABILITY PRESERVATIVE) | ( ) IMMERSION SILVER | ( ) SOFT WIRE BONDABLE GOLD 30-50 MICRO INCHES OF SOFT WIRE | ( ) EDGE CONNECTOR FINGERS ARE TO BE PLATED WITH 100 MICRO-INCHES(.0001") OF LOW STRESS | THICKNESS & TRACE WIDTHS TO MEET THE IMPEDANCE REQUIREMENT. IF SPECIFIED, THE VENDOR MUST | TRACE WIDTH & SPACING THAT IMPACT THE REQUIREMENTS MUST HAVE WRITTEN APPROVAL FROM ADI. | MINIMUM BARREL PLATING OF 0.001 INCHES. PLATED HOLES SHALL NOT BE ROUGH OR IRREGULAR SO AS TO | SOLDERMASK OVER BARE COPPER OR BARE GOLD (BOTH SIDES) TO MEET IPC-SM-840. | IF PRESENT,DO NOT MODIFY SOLDERMASK DEFINED PADS (MASK OPENINGS LESS THAN COPPER PAD) WITHOUT APPROVAL. | MEET THE REQUIREMENTS LISTED IN THE IMPEDANCE TABLE. ANY ADJUSTMENT MADE TO THE DEFINED STACKUP, | PROCESSES. FINISHED THICKNESS MEASURED FROM TOP COPPER TO BOTTOM COPPER. | (X)  ISOLA 370HR OR S1000-2 OR IT180 OR EQUIVALENT | ( )  ISOLA-FR408HR OR EQUIVALENT | ( )  ISOLA IS410 | ( )  MEGTRON 6 | ( )  NELCO-4000-13 | ( )  ROGERS 4350B | ( ) ROGERS 3003 | ( ) ARLON 85N | ( ) EM370D | ( )  OTHER ________________________ | UL FLAMMABILITY RATING 94V-0. BOARD MATERIAL & CONSTRUCTION SHALL MEET THE REQUIREMENTS OF UL796/UL796F. | BONDABLE GOLD OVER 100-150 MICRO INCHES OF NICKEL | NICKEL UNDER 30 MICRO-INCHES (.0003') OF GOLD | 0.100 INCH CLEARANCE FROM ALL COPPER FEATURES, | THE STARTING COPPER WEIGHT/THICKNESS CAN VARY AS LONG AS THE FINISHED COPPER | WEIGHT/THICKNESS IS NOT LESS THAN THE SPECIFIED VALUE. | UNLESS OTHERWISE SPECIFIED | WORKMANSHIP SHALL CONFORM TO IPC-A-600, CLASS 2. | 21.  INTENTIONAL SHORTS: | 17.  FINAL ELECTRICAL TEST TO BE PERFORMED USING PROVIDED IPC-D-356A NETLIST OR ODB++ FORMAT FILE. | 22.  PEMNUTS: | 23.  MANUFACTURER TO ETCH/STAMP WITH PERMANENT NON-CONDUCTIVE INK | ON SECONDARY SIDE UNLESS OTHERWISE SPECIFIED: | 18.  A TIME DOMAIN REFLECTOMETER REPORT (TDR) FOR EACH IMPEDANCE CONTROLLED LAYER & A CERTIFICATE | 19.  IF PRESENT, ALL BLIND/BURIED VIAS WITH AN ASPECT RATIO <1:1 TO BE PLATED SHUT WITH COPPER WHEN | 20.  FOR VIA FILL INFORMATION REFER TO DRILL CHART: | 25. PANELIZATION: | 27.  MINIMUM DESIGN LINE WIDTH IS .008 INCH. | 28.  MINIMUM DESIGN LINE SPACING IS .008 INCH. | IS ACCEPTABLE, ALL OTHER INSTANCES MUST BE REPORTED. | IF AN INTENTIONAL SHORT REPORT IS SUPPLIED AND DOES NOT MATCH THE FAB DATA THEN | THE PCB SHALL HAVE A VERIFICATION STAMP. | ( )  NON-CONDUCTIVE EPOXY FILL ALL 0.XXXX INCHES DRILLED VIAS | ( )  COPPER FILL ALL 0.XXXX INCHES DRILLED VIAS | ( ) PEMNUTS TO BE INSTALLED BY FABRICATOR | ( ) PEMNUTS NOT TO BE INSTALLED BY FABRICATOR | (X) NOT APPLICABLE | USED AS VIA-IN-PAD OR AS A STACKED VIA. BLIND/BURIED VIAS WITH AN ASPECT RATIO >1:1 TO BE FILLED | A. UL CODE-FLAMMABILITY RATING FOR THOSE APPROVED MATERIALS(IF APPLICABLE) | B. DATE CODE | C. LOT NUMBER | D. MANUFACTURER LOGO | BOARDS TO BE SHIPPED IN ARRAY AND KEPT INTACT | PANEL TO BE SUBJECTED TO CUSTOMERS APPROVAL | PANEL SOLDER PASTE STENCIL GERBER TO BE PROVIDED TO ANALOG | CAN'T BE PERFORMED BECAUSE THE TRACE LENGTH IS TOO SHORT ON THE OUTER LAYERS AT THE PIN ESCAPES | ADI APPROVAL IS REQUIRED. | OF COMPLIANCE SHALL BE PROVIDED BY VENDOR AT TIME OF SHIPMENT. INSTANCES WHERE TDR TESTING | WITH NON-CONDUCTIVE EPOXY. | x | TOOLING: | FINISH: | NOTES: | MATERIAL: | TESTING: | MISCELLANEOUS: | 6-LAYER STACK-UP | A | Initial Release | CR | NOTE: ALL IMPEDANCE TOLERANCE +/-10% | LAYER | L1 | SE = SINGLE ENDED, DP = DIFFERENTIAL PAIR | 50 OHMS SE | IMPEDANCE | REFERENCE | L2 | LINE WIDTH | 4MILS | SPACE | N/A | EVAL-LT8210-1-AZ | IMPEDANCE TABLE
DIMENSION: - | " " | (REF)
User.31: L2 GND | 08-      -06
User.32: L3 SIG | 08-      -07
User.33: L4 GND | 08-      -08
User.34: L5 VCC | 08-      -09
User.37: IN | OUT | - | POWER | SUPPLY | A | I | V | LOAD | +
User.45: FIGURE | SIZE | 10.0 | 12.0 | 30.0 | 40.0 | 191.0 | 125.0 | PLATED | NON-PLATED | DRILL CHART: TOP to BOTTOM | ALL UNITS ARE IN MILS | QTY | 328 | 6707 | 28 | 8 | 6 | TOLERANCE/NOTES
